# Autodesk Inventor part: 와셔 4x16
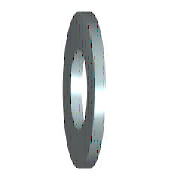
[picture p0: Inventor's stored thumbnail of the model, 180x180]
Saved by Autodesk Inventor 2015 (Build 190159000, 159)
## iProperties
IsCustomPart: 1
Created: 2012-02
Part Number: 와셔 4x16
Material: 강철, 연강
Description: 미터법 평면 와셔
Document SubType Name: Modeling
Standard: ANSI B18.22M
Designer: mduedu
Standard Revision: 1999
Standards Organization: ANSI
Language: ko-KR
Size Designation: 4 W
Categories: <MemberInstance><Categories><Category DisplayName="조임쇠" InternalName="e4da775c-781d-43d5-af7c-5136215cf5a6" Mnemonic="FSTN"><Category DisplayName="와셔" InternalN
Density: 7.85 g/cm^3
Appearance: 파란색 - 벽 페인트 - 광택
Mass: 3.31693 g
Surface Area: 5.16996 cm^2
Volume: 0.422539 cm^3
Author: mduedu
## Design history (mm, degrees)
sketch "스케치"
  geometry: C1 r 8 at (0, 0); C2 r 2.35 at (0, 0); 1 further point
  constraints: 2 centre point, 2 coincident
  dimensions: "d0" = 4.7 diameter of C2 (= SD1); "d1" = 16 diameter of C1 (= SD2)
extrude "본체" new body sketch "스케치" distance "d2" = 2.3 (= SD); taper "d3" = 0 deg
workaxis "Work Axis1"
workplane "Work Plane1"
body "Solid1"
other parameters: "SD1" = 4.7 [user parameter; used in 1 equation term], "SD2" = 16 [user parameter; used in 1 equation term], "SD" = 2.3 [user parameter; used in 1 equation term], "d4" = 0, "d5" = 0, "d6" = 0, "d7" = 0, "NND" = 4 [user parameter]
